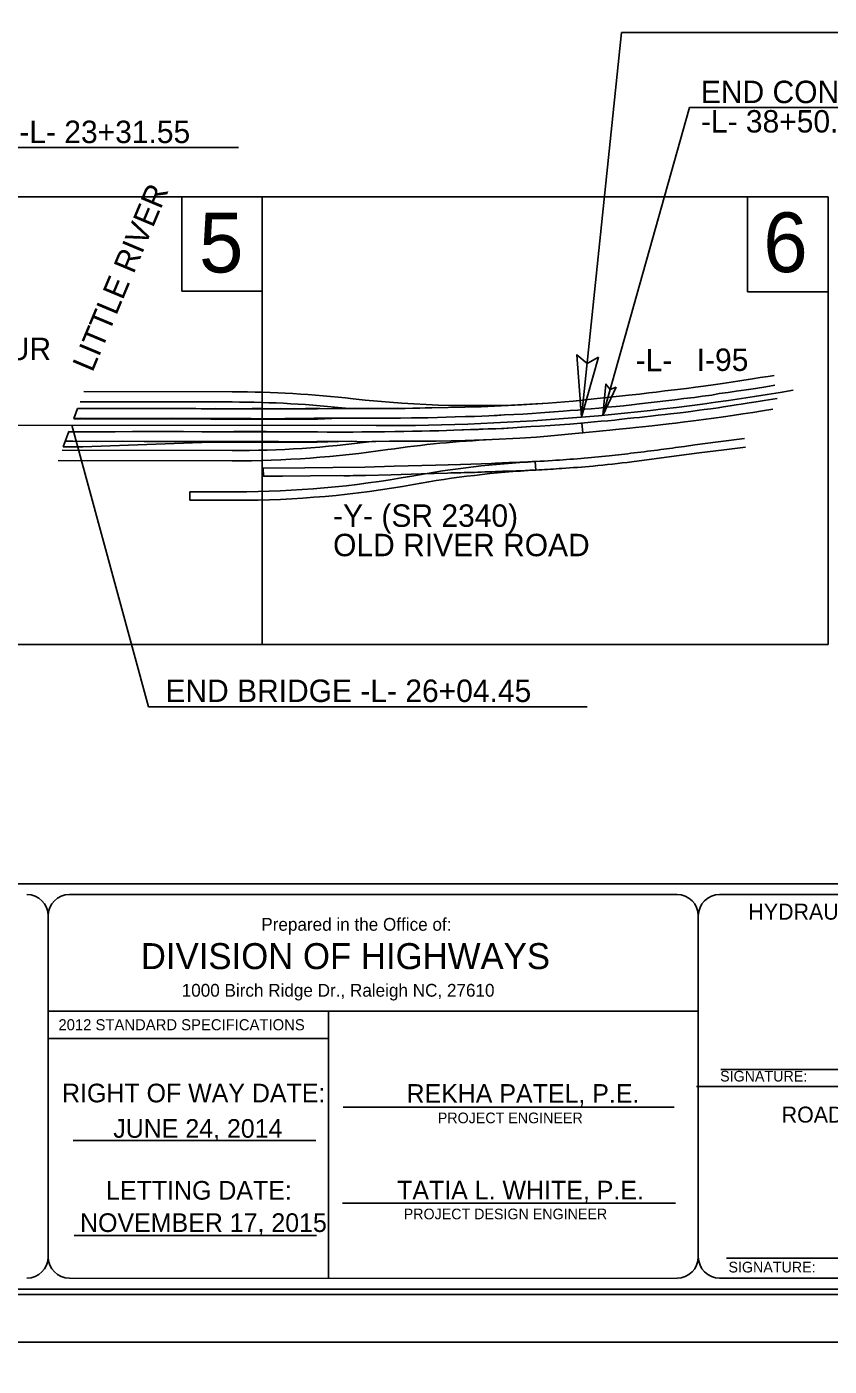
# Model space of a CAD drawing. Extents: x 2241278 to 2254132, y 649924 to 670434.
# Drawn here: x 2249319 to 2251201, y 660843 to 663984 of the extents above; entities that cross this region are included whole.
import ezdxf

# ---------------------------------------------------------------- set-up
doc = ezdxf.new("R2010")
doc.units = 0
for name, color, linetype in [('Default', 7, 'Continuous'), ('Pattern 4', 7, 'Continuous'), ('Prop DSN Text', 7, 'Continuous'), ('Prop Horizontal Alignment', 7, 'Continuous'), ('Prop Horizontal Alignment Station Label', 7, 'Continuous'), ('Prop RDY Alternate Text Yellow', 7, 'Continuous'), ('Prop Shade Heavy', 7, 'Continuous'), ('Prop Terminator CELL', 7, 'Continuous'), ('Sheet Cutting Line CELL', 7, 'Continuous'), ('Sheet Data Field CELL', 7, 'Continuous'), ('Sheet Plot Border Inside CELL', 7, 'Continuous'), ('Sheet Plot Border Outside CELL', 7, 'Continuous'), ('Sheet Title CELL', 7, 'Continuous')]:
    doc.layers.add(name, color=color, linetype=linetype)

msp = doc.modelspace()

# ---------------------------------------------------------------- linework, layer by layer
at = {"layer": 'Pattern 4'}
msp.add_line((2249429.2, 663066.1), (2249437.8, 663089.3), dxfattribs=at)
for points in [[(2250708.6, 663117.9), (2250729.7, 663120.6), (2250756, 663123.2), (2250778.1, 663125.8), (2250795.2, 663127.9), (2250815.5, 663130.6), (2250838, 663132.8), (2250865.7, 663136.3), (2250887.2, 663139.3), (2250906, 663141.6), (2250934.2, 663145.9), (2250950.6, 663147.8), (2250971, 663150.9), (2250995.6, 663154.6), (2251021.2, 663158.9), (2251039.2, 663162.2), (2251057.4, 663164.4), (2251071.8, 663166.5)], [(2250576.4, 663083), (2250576.6, 663083), (2250593.4, 663084.2), (2250611.4, 663085.7), (2250627.9, 663087.3), (2250642.4, 663088.7), (2250660.8, 663090.2), (2250680.1, 663092.4), (2250700.8, 663093.9), (2250718.3, 663095.8), (2250737.6, 663098.2), (2250755.7, 663099.9), (2250776.5, 663102.4), (2250797.3, 663104.6), (2250817.8, 663107), (2250838.8, 663109.8), (2250859.7, 663112.4), (2250885.1, 663115.2), (2250903.6, 663118.2), (2250925.4, 663120.9), (2250942.3, 663124.2), (2250964.1, 663127), (2250982.5, 663129.9), (2251005.9, 663132.8), (2251027.6, 663136.4), (2251052.3, 663140.3), (2251073.1, 663143.7)], [(2250268.5, 663091), (2250384.1, 663093.1), (2250478.7, 663097.6), (2250541.3, 663102), (2250600, 663106.4), (2250656.5, 663112.6), (2250708.6, 663117.9)], [(2250579.6, 663051.9), (2250592.3, 663052.8), (2250609.4, 663054.1), (2250626.9, 663055.9), (2250649.5, 663057.9), (2250665.6, 663059.3), (2250681.4, 663060.6), (2250697.8, 663062.1), (2250708.5, 663063.4), (2250727.1, 663065.4), (2250742.2, 663067.1), (2250755.7, 663068.5), (2250768.1, 663069.8), (2250781.8, 663071.4), (2250799.9, 663073.3), (2250816, 663075.3), (2250828.8, 663076.7), (2250844.1, 663078.4), (2250857.9, 663080.1), (2250875.9, 663082.2), (2250895.9, 663085), (2250907.2, 663086.6), (2250922.8, 663088.6), (2250940.5, 663091), (2250952.5, 663092.8), (2250968.5, 663095.4), (2250982.4, 663097.5), (2250994.4, 663099.5), (2251013.2, 663102.5), (2251029.6, 663105.1), (2251048.3, 663107.9), (2251068.9, 663111.2), (2251078.4, 663112.6)], [(2249429.2, 663066.1), (2249445.2, 663066.4), (2249483.7, 663066.1), (2249519.3, 663066), (2249558, 663066.1), (2249596.4, 663066), (2249629.2, 663066), (2249658.1, 663066.2), (2249686.8, 663066), (2249722.1, 663065.8), (2249765, 663065.9), (2249803.3, 663066), (2249845.4, 663065.5), (2249887.4, 663065.3), (2249923.7, 663065.6), (2249959.8, 663065.9), (2249992.8, 663066.3), (2250035, 663066.3), (2250074.8, 663066.2), (2250114.9, 663066.4), (2250156.1, 663066.4), (2250195.5, 663066.8), (2250221.2, 663067.4), (2250240.7, 663067.6), (2250259.5, 663067.4), (2250282.4, 663068), (2250302.1, 663069), (2250323.1, 663069.5), (2250347.9, 663070.3), (2250368.7, 663070.6), (2250386.4, 663071.5), (2250402.4, 663072.2), (2250422.3, 663072.9), (2250439.2, 663074.4), (2250461.2, 663075.4), (2250482, 663076), (2250503.9, 663077.5), (2250523.7, 663078.9), (2250543.7, 663080.7), (2250544.4, 663080.7)], [(2250268.5, 663091), (2250253.1, 663090.8), (2250240.7, 663090.2), (2250224.4, 663090), (2250206.4, 663089.6), (2250187.7, 663089.7), (2250172.3, 663089.3), (2250150.9, 663089), (2250131.8, 663089.1), (2250114.3, 663089.2), (2250095.9, 663089), (2250080.3, 663088.9), (2250064.8, 663089.4), (2250050.9, 663089.2), (2250036.5, 663089), (2250021.7, 663088.8), (2250006, 663089), (2249989, 663089), (2249972.4, 663089), (2249959.7, 663088.7), (2249947.8, 663089), (2249939.8, 663088.7), (2249929.3, 663088.7), (2249914.4, 663089), (2249900.8, 663088.6), (2249890.4, 663088.5), (2249881.1, 663088.7), (2249871.8, 663088.9), (2249847, 663089.1), (2249833.1, 663088.7), (2249823, 663088.7), (2249810, 663088.6), (2249792.6, 663088.4), (2249776.5, 663088.7), (2249762.2, 663089), (2249749.3, 663088.8), (2249739.6, 663088.6), (2249728.1, 663088.7), (2249715.2, 663089), (2249703.9, 663088.9), (2249692, 663089), (2249680.9, 663089), (2249671.4, 663089), (2249662.1, 663089.2), (2249651.9, 663089), (2249641.3, 663089), (2249630.9, 663088.9), (2249619.7, 663089), (2249606.3, 663089.1), (2249594.2, 663089.2), (2249585.9, 663089.2), (2249576.8, 663089.1), (2249566.7, 663089.2), (2249555.9, 663089.2), (2249544.4, 663089.4), (2249533.1, 663089.1), (2249520.4, 663089.5), (2249508, 663089.3), (2249497.5, 663089.2), (2249486.9, 663089), (2249478.3, 663089.3), (2249466.8, 663089.2), (2249456.1, 663089.1), (2249444, 663089.2), (2249437.8, 663089.3)], [(2250544.4, 663080.7), (2250576.4, 663083)], [(2250621.2, 663032.1), (2250654.1, 663035), (2250670.2, 663036.8), (2250686.4, 663038.3), (2250700.1, 663039.6), (2250715.6, 663041.3), (2250733, 663043.3), (2250746.8, 663044.5), (2250762.9, 663046.4), (2250785.6, 663048.6), (2250804.7, 663051), (2250824.8, 663053.6), (2250840, 663055), (2250861.8, 663058), (2250882.8, 663060.7), (2250905.8, 663063.4), (2250930, 663066.9), (2250952.5, 663069.7), (2250974, 663073), (2250998.4, 663076.5), (2251021.5, 663080.2), (2251044.2, 663083.7), (2251068.2, 663087.8)], [(2250546.4, 663049.4), (2250522.1, 663048), (2250501.2, 663046.7), (2250479, 663045.2), (2250458.9, 663043.8), (2250437.3, 663042.7), (2250418.7, 663041.8), (2250400.6, 663041.7), (2250377.9, 663039.9), (2250359.8, 663039.6), (2250343.2, 663039), (2250320.5, 663038.2), (2250303.4, 663037.6), (2250284.8, 663037), (2250264.2, 663036.6), (2250245.3, 663036.2), (2250223.6, 663035.8), (2250203.4, 663035.4), (2250182.3, 663035.2), (2250157.4, 663034.7), (2250143.9, 663034.4), (2250122.9, 663034.3), (2250104.8, 663034.5), (2250084, 663033.9), (2250066.6, 663033.4), (2250058.4, 663033.8), (2250023.4, 663034), (2249987.1, 663034.2), (2249957.9, 663034.9), (2249924.5, 663034.5), (2249880.4, 663035), (2249843.5, 663035), (2249804.3, 663035.2), (2249765.1, 663034.8), (2249729, 663034.9), (2249686.2, 663035.2), (2249647.4, 663035.4), (2249608.8, 663035.2), (2249566.9, 663035.1), (2249525.9, 663034.8), (2249490.9, 663034.7), (2249443.6, 663034.4), (2249417.5, 663034.4)], [(2250546.4, 663049.4), (2250579.7, 663051.9)], [(2249409.4, 663012.5), (2249427.8, 663012.5), (2249482.1, 663012), (2249543.8, 663012.3), (2249594, 663012), (2249639.6, 663012), (2249672.4, 663011.6), (2249732.3, 663011.7), (2249825.3, 663011.7), (2249909.5, 663011.6), (2249957.6, 663011), (2249999.3, 663011.5), (2250031.6, 663011.5), (2250080.5, 663012.3), (2250105.1, 663011.4), (2250137.4, 663012.1), (2250169.5, 663012.3)], [(2250169.5, 663012.3), (2250279.3, 663013), (2250314.1, 663013.4), (2250347.3, 663014.3), (2250390.1, 663015.8), (2250410.3, 663016.2), (2250475.3, 663019.4), (2250514, 663022.1), (2250540.3, 663024.5), (2250621.2, 663032.1)], [(2251001.7, 663018.7), (2250940.2, 663010.7), (2250885.9, 663003.7), (2250861.2, 663000.3)], [(2250738.1, 662964.1), (2250790.2, 662971.2), (2250842.7, 662978), (2250895.8, 662985.2), (2250954.7, 662992.4), (2251004.7, 662998.8)], [(2250408.7, 662960.6), (2250336.1, 662958.2), (2250278.5, 662956.4), (2250180.3, 662953.8), (2250111.5, 662951.8), (2250036.9, 662951.2), (2249971.2, 662950.3), (2249873.2, 662949.2), (2249873.7, 662930.6), (2249918.4, 662930.3), (2249984, 662931.2), (2250054.6, 662931.8)], [(2250113.5, 662932.4), (2250173.5, 662934), (2250243.4, 662936.4), (2250305.3, 662937.8)]]:
    msp.add_lwpolyline(points, dxfattribs=at)
msp.add_ellipse((2250069.4, 664482.8), major_axis=(-1098.8, -1095.1), ratio=0.999747, start_param=0.777697, end_param=0.815691, dxfattribs=at)
for points in [[(2250861.2, 663000.3), (2250805.6, 662992.9), (2250743, 662985), (2250684.4, 662978.2), (2250617.9, 662972.1), (2250551.5, 662967.2), (2250475.1, 662963.3), (2250408.7, 662960.6)], [(2250305.3, 662937.8), (2250368.5, 662939.5), (2250434.7, 662941.9), (2250519.8, 662945.3), (2250573.9, 662948.7), (2250646.8, 662954.2), (2250738.1, 662964.1)]]:
    msp.add_spline(points, degree=3, dxfattribs=at)
at = {"layer": 'Prop DSN Text'}
for p, q in [((2251198.4, 663585.5), (2247330.5, 663585.4)), ((2249682.5, 663364.2), (2249682.5, 663585.5)), ((2249870.7, 663585.5), (2249870.8, 662535.4)), ((2251009.2, 663362.9), (2251009.2, 663585.5)), ((2251198.4, 663585.5), (2251198.4, 662535.4)), ((2249870.8, 663364.2), (2249682.5, 663364.2)), ((2251198.4, 663362.9), (2251009.2, 663362.9)), ((2250616.5, 663108.2), (2250618.3, 663086.4)), ((2249428.8, 663065), (2249437.7, 663089)), ((2249437.7, 663089), (2249437.7, 663089)), ((2249750.3, 663088.6), (2250000.3, 663088.3)), ((2250000.3, 663088.3), (2250050.3, 663089.2)), ((2250050.3, 663066.2), (2250000.3, 663064.3)), ((2249404.4, 662999), (2249417.7, 663035)), ((2249417.7, 663035), (2249417.7, 663035)), ((2250000.3, 663064.3), (2249750.3, 663064.6)), ((2249750.3, 663034.6), (2250000.3, 663034.3)), ((2250620.9, 663055.2), (2250622.8, 663032.2)), ((2249750.2, 663010.6), (2249450.2, 662999)), ((2250000.2, 663010.3), (2249750.2, 663010.6)), ((2250050.2, 663011.8), (2250000.2, 663010.3)), ((2250000.3, 663034.3), (2250050.3, 663033.9)), ((2250512.4, 662944.8), (2250511.3, 662964.7)), ((2249809.3, 662893.9), (2249701.1, 662894)), ((2249701.1, 662894), (2249701.1, 662874)), ((2249701.1, 662874), (2249809.3, 662873.9)), ((2247330.5, 662535.4), (2251198.4, 662535.4))]:
    msp.add_line(p, q, dxfattribs=at)
for points in [[(2250050.3, 663089.2), (2250064.8, 663089.4), (2250080.3, 663088.9), (2250095.9, 663089), (2250114.3, 663089.2), (2250131.8, 663089.1), (2250150.9, 663089), (2250187.7, 663089.7), (2250206.4, 663089.6), (2250224.4, 663090), (2250240.7, 663090.2), (2250253.1, 663090.8), (2250268.5, 663091), (2250384.1, 663093.1), (2250478.7, 663097.6), (2250541.3, 663102), (2250600, 663106.4), (2250616.5, 663108.2)], [(2249437.7, 663089), (2249750.3, 663088.6)], [(2250618.3, 663086.4), (2250611.4, 663085.7), (2250593.4, 663084.2), (2250576.4, 663083), (2250543.7, 663080.7), (2250523.7, 663078.9), (2250503.9, 663077.5), (2250482, 663076), (2250461.2, 663075.4), (2250439.2, 663074.4), (2250402.4, 663072.2), (2250368.7, 663070.6), (2250347.9, 663070.3), (2250323.1, 663069.5), (2250302.1, 663069), (2250282.4, 663068), (2250259.5, 663067.4), (2250240.7, 663067.6), (2250221.2, 663067.4), (2250195.5, 663066.8), (2250156.1, 663066.4), (2250114.9, 663066.4), (2250050.3, 663066.2)], [(2249417.7, 663035), (2249750.3, 663034.6)], [(2249750.3, 663064.6), (2249428.8, 663065)], [(2250050.3, 663033.9), (2250084, 663033.9), (2250122.9, 663034.3), (2250143.9, 663034.4), (2250182.3, 663035.2), (2250203.4, 663035.4), (2250223.6, 663035.8), (2250245.3, 663036.2), (2250284.8, 663037), (2250320.5, 663038.2), (2250359.8, 663039.6), (2250400.6, 663041.7), (2250418.7, 663041.8), (2250458.9, 663043.8), (2250501.2, 663046.7), (2250522.1, 663048), (2250546.4, 663049.4), (2250579.6, 663051.9), (2250592.3, 663052.8), (2250609.4, 663054.1), (2250620.9, 663055.2)], [(2250622.8, 663032.2), (2250621.2, 663032.1), (2250540.3, 663024.5), (2250514, 663022.1), (2250475.3, 663019.4), (2250410.3, 663016.2), (2250390.1, 663015.8), (2250347.3, 663014.3), (2250314.1, 663013.4), (2250279.3, 663013), (2250169.5, 663012.3), (2250137.4, 663012.1), (2250105.1, 663011.4), (2250080.5, 663012.3), (2250050.2, 663011.8)], [(2249450.2, 662999), (2249404.4, 662999)]]:
    msp.add_lwpolyline(points, dxfattribs=at)
for centre, radius, start, end in [((2250635.5, 660658.1), 2310, 93.0808, 100.3057), ((2250635.5, 660658.1), 2290, 93.0808, 100.3057), ((2249812.5, 665183.9), 2290, 269.9198, 280.3057), ((2249812.5, 665183.9), 2310, 269.9198, 280.3057)]:
    msp.add_arc(centre, radius, start, end, dxfattribs=at)
at = {"layer": 'Prop Horizontal Alignment'}
msp.add_line((2247428.2, 663052.4), (2250138, 663049.1), dxfattribs=at)
msp.add_arc((2250144.8, 668778.7), 5729.6, 269.9321, 279.7616, dxfattribs=at)
at = {"layer": 'Prop Horizontal Alignment Station Label'}
msp.add_line((2250669.5, 663073.2), (2250873, 663794.9), dxfattribs=at)
at = {"layer": 'Prop RDY Alternate Text Yellow'}
for p, q in [((2250713.3, 663970.9), (2250619.7, 663068.9)), ((2250713.3, 663970.9), (2252608.4, 663970.9)), ((2250873, 663794.9), (2251656.1, 663794.9)), ((2248751.6, 663701.3), (2249815.4, 663701.3)), ((2249424.7, 663050), (2249604.1, 662389.4)), ((2249604.1, 662389.4), (2250632.9, 662389.4))]:
    msp.add_line(p, q, dxfattribs=at)
at = {"layer": 'Prop Shade Heavy'}
for p, q in [((2249452.5, 663129), (2249452.5, 663129)), ((2249392.6, 662967), (2249392.6, 662967))]:
    msp.add_line(p, q, dxfattribs=at)
for points in [[(2249452.5, 663129), (2249800.7, 663128.5)], [(2249800.7, 663104.5), (2249443.6, 663105)], [(2250541.3, 663102), (2250478.7, 663097.6), (2250384.1, 663093.1), (2250268.5, 663091), (2250253.1, 663090.8), (2250240.7, 663090.2), (2250206.4, 663089.6), (2250172.3, 663089.3), (2250150.9, 663089), (2250131.8, 663089.1), (2250095.9, 663089), (2250075, 663089.1)], [(2250410.3, 663016.2), (2250390.1, 663015.8), (2250347.3, 663014.3), (2250314.1, 663013.4), (2250279.3, 663013), (2250169.5, 663012.3), (2250137.4, 663012.1), (2250128.4, 663011.9)], [(2249800.2, 662990.5), (2249401.6, 662991.4)], [(2249392.6, 662967), (2249800.2, 662966.5)]]:
    msp.add_lwpolyline(points, dxfattribs=at)
for centre, radius, start, end in [((2249797.8, 660616.5), 2512, 83.4518, 89.9321), ((2249797.8, 660616.5), 2488, 83.6031, 89.9321), ((2250368, 665583.9), 2488, 263.4518, 273.9963), ((2249803.2, 665478.5), 2488, 269.9321, 277.5112), ((2250524.8, 660530.9), 2488, 92.6379, 98.2981), ((2249803.2, 665478.5), 2512, 269.9321, 278.2981)]:
    msp.add_arc(centre, radius, start, end, dxfattribs=at)
at = {"layer": 'Prop Terminator CELL'}
for points in [[(2250659.3, 663209.5), (2250619.7, 663068.9), (2250609.2, 663215.5), (2250632.8, 663194.6)], [(2250701, 663139.2), (2250669.5, 663073.2), (2250676.9, 663146.4), (2250686.7, 663134)]]:
    msp.add_lwpolyline(points, close=True, dxfattribs=at)
at = {"layer": 'Sheet Cutting Line CELL'}
for p, q in [((2244558.8, 660899.2), (2252978.8, 660899.2)), ((2252978.8, 660899.2), (2244558.8, 660899.2))]:
    msp.add_line(p, q, dxfattribs=at)
at = {"layer": 'Sheet Plot Border Inside CELL'}
msp.add_lwpolyline([(2244623.8, 661011.4), (2252956.3, 661011.4), (2252956.3, 666286.9), (2244623.8, 666286.9)], close=True, dxfattribs=at)
at = {"layer": 'Sheet Plot Border Outside CELL'}
for points in [[(2252978.8, 666399.1), (2244558.8, 666399.1), (2244558.8, 660899.2), (2252978.8, 660899.2)], [(2244558.8, 655399.2), (2252978.8, 655399.2), (2252978.8, 660899.2), (2244558.8, 660899.2)]]:
    msp.add_lwpolyline(points, close=True, dxfattribs=at)
at = {"layer": 'Sheet Title CELL'}
for p, q in [((2245718.8, 661974.2), (2252818.8, 661974.2)), ((2249418.8, 661949.2), (2250843.8, 661949.2)), ((2250943.8, 661949.2), (2251942.6, 661949.2)), ((2249368.8, 661899.2), (2249368.8, 661099.2)), ((2250893.8, 661099.1), (2250893.8, 661899.1)), ((2250893.8, 661675.4), (2249368.8, 661675.4)), ((2250026.5, 661675.4), (2250026.5, 661049.2)), ((2250026.5, 661611.6), (2249368.8, 661611.7)), ((2249837, 661611.7), (2249837, 661611.7)), ((2250946.2, 661539.2), (2251667.5, 661539.2)), ((2250889.3, 661499.3), (2251992.6, 661499.3)), ((2250061, 661450.4), (2250836.8, 661450.4)), ((2249996.5, 661372.4), (2249427.8, 661372.4)), ((2249712, 661372.4), (2249712, 661372.4)), ((2250059.3, 661225.4), (2250840.5, 661225.4)), ((2249998.5, 661149.4), (2249429.8, 661149.4)), ((2250960, 661096.4), (2251667.5, 661096.4))]:
    msp.add_line(p, q, dxfattribs=at)
for points in [[(2245443.8, 661024.1), (2252843.8, 661024.1)], [(2249418.8, 661049.2), (2250843.8, 661049.1)], [(2250943.8, 661049.2), (2251942.6, 661049.2)]]:
    msp.add_lwpolyline(points, dxfattribs=at)
for centre, start, end in [((2249318.8, 661899.4), 0, 90), ((2249418.8, 661899.4), 90, 180), ((2250843.8, 661899.4), 0, 90), ((2250943.8, 661899.4), 90, 180), ((2249318.8, 661099.4), 270, 360), ((2249418.8, 661099.4), 180, 270), ((2250843.8, 661099.4), 270, 360), ((2250943.8, 661099.4), 180, 270)]:
    msp.add_arc(centre, 50, start, end, dxfattribs=at)

# ---------------------------------------------------------------- texts
at = {"layer": 'Default'}
msp.add_text('LITTLE RIVER', height=52.594, rotation=67.2989, dxfattribs=at).set_placement((2249472.8, 663172.5))
at = {"layer": 'Prop RDY Alternate Text Yellow'}
for s, height, p in [('END CONSTRUCTION', 52.594, (2250899.8, 663805.5)), ('-L- 38+50.00', 52.594, (2250899.8, 663736.5)), ('BEGIN BRIDGE -L- 23+31.55', 52.594, (2248773.7, 663711.8)), ('5', 140, (2249722.7, 663408.3)), ('6', 140, (2251046.2, 663409.1)), ('DETOUR', 52.59, (2249078.9, 663202.7)), ('-L-', 52.59, (2250746.8, 663176.5)), ('I-95', 52.59, (2250890, 663177.3)), ('-Y- (SR 2340)', 52.594, (2250037.2, 662811.7)), ('OLD RIVER ROAD', 52.594, (2250037.2, 662742.8)), ('END BRIDGE -L- 26+04.45', 52.594, (2249643.9, 662400.9))]:
    msp.add_text(s, height=height, dxfattribs=at).set_placement(p)
at = {"layer": 'Sheet Data Field CELL'}
for s, p in [('REKHA PATEL, P.E.', (2250209.3, 661460.8)), ('JUNE 24, 2014', (2249521.6, 661378.8)), ('TATIA L. WHITE, P.E.', (2250187.4, 661234.2)), ('NOVEMBER 17, 2015', (2249443.7, 661157.9))]:
    msp.add_text(s, height=43.751, dxfattribs=at).set_placement(p)
at = {"layer": 'Sheet Title CELL'}
for s, height, p in [(' HYDRAULICS ENGINEER', 37.5, (2250997.3, 661890.4)), ('Prepared in the Office of:', 29.997, (2249868.8, 661864.4)), ('DIVISION OF HIGHWAYS', 60.936, (2249586.2, 661774.4)), ('1000 Birch Ridge Dr., Raleigh NC, 27610', 30, (2249682.1, 661709.7)), ('2012 STANDARD SPECIFICATIONS', 26, (2249393, 661630.9)), ('SIGNATURE:', 25, (2250944.9, 661510.8)), ('RIGHT OF WAY DATE: ', 43.749, (2249401.5, 661461.9)), ('PROJECT ENGINEER', 24.998, (2250282.8, 661412.9)), ('ROADWAY DESIGN', 37.497, (2251089.3, 661414.4)), ('LETTING DATE:', 43.749, (2249504.8, 661233.7)), ('PROJECT DESIGN ENGINEER', 24.998, (2250202.8, 661187.6)), ('SIGNATURE:', 25, (2250964.5, 661062.9))]:
    msp.add_text(s, height=height, rotation=360, dxfattribs=at).set_placement(p)

doc.saveas('drawing.dxf')
